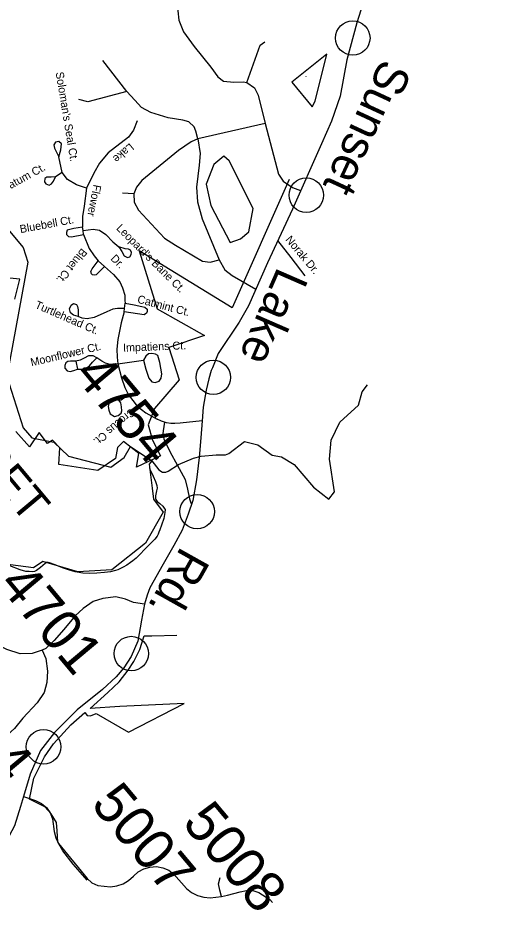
# Model space of a CAD drawing. Extents: x 2054826 to 2060231, y 685508 to 690809.
# Drawn here: x 2058824.2 to 2058951.1, y 689444.4 to 689682.8 of the extents above; entities that cross this region are included whole.
import ezdxf

# ---------------------------------------------------------------- set-up
doc = ezdxf.new("R2010")
doc.units = 0
for name, color, linetype in [('Default', 7, 'Continuous'), ('Old_Level_10', 7, 'Continuous'), ('Old_Level_11', 7, 'Continuous'), ('Old_Level_21', 7, 'Continuous'), ('Old_Level_31', 7, 'Continuous'), ('Old_Level_32', 7, 'Continuous'), ('Old_Level_35', 7, 'Continuous'), ('Old_Level_48', 7, 'Continuous'), ('Old_Level_49', 7, 'Continuous'), ('Old_Level_50', 7, 'Continuous'), ('Old_Level_56', 7, 'Continuous'), ('Old_Level_59', 7, 'Continuous'), ('Old_Level_60', 7, 'Continuous'), ('Old_Level_62', 7, 'Continuous'), ('Old_Level_8', 7, 'Continuous'), ('Sheet Title CELL', 7, 'Continuous')]:
    doc.layers.add(name, color=color, linetype=linetype)

msp = doc.modelspace()

# ---------------------------------------------------------------- linework, layer by layer
at = {"layer": 'Default'}
for centre in [(2058913.43, 689677.45), (2058901.04, 689635.59), (2058876.29, 689587.06), (2058871.97, 689551.29), (2058854.42, 689513.49), (2058831.05, 689488.65)]:
    msp.add_circle(centre, 4.59, dxfattribs=at)
at = {"layer": 'Old_Level_31'}
msp.add_line((2058872.52, 689565.68), (2058872.52, 689565.68), dxfattribs=at)
at = {"layer": 'Old_Level_32'}
for points in [[(2058916.65, 689688.35), (2058914.48, 689681.47), (2058911.85, 689671.65), (2058910.05, 689661.96), (2058907.79, 689655.31), (2058905.13, 689649.29), (2058897.33, 689631.9), (2058890.75, 689617.53), (2058885.69, 689606.14), (2058883.17, 689601.8), (2058877.58, 689593.44)], [(2058877.58, 689593.44), (2058876.06, 689589.61), (2058875.73, 689588.92), (2058875.13, 689586.68), (2058874.41, 689583.61), (2058873.61, 689579.15), (2058873.28, 689575.49)], [(2058873.28, 689575.49), (2058867.45, 689574.9), (2058866.01, 689574.73), (2058865, 689574.77), (2058863.81, 689574.96), (2058862.45, 689575.39), (2058861.33, 689575.93)], [(2058873.28, 689575.49), (2058872.95, 689570.96), (2058872.52, 689565.68)], [(2058872.52, 689565.68), (2058871.84, 689559.76), (2058870.78, 689554.28), (2058869.62, 689550.65), (2058868, 689546.38), (2058865.73, 689542.26), (2058862.9, 689537.28), (2058859.39, 689531), (2058858.63, 689529.02), (2058857.94, 689526.64)], [(2058857.94, 689526.64), (2058857.16, 689522.38), (2058856.15, 689516.79), (2058854.37, 689512.69), (2058852.46, 689509.69), (2058850.36, 689507.28), (2058846.78, 689503.88), (2058840.04, 689498.54), (2058833.98, 689492.46), (2058830.22, 689487.64), (2058827.48, 689481.4), (2058825.7, 689475.43)], [(2058857.94, 689526.64), (2058855.01, 689527.07), (2058852.87, 689527.95), (2058850.34, 689528.58), (2058846.85, 689528.19), (2058844.3, 689527.4), (2058841.65, 689525.45), (2058839.5, 689523.54), (2058836.43, 689519.9), (2058833.9, 689516.96), (2058831.67, 689514.83), (2058830.71, 689514.37)], [(2058830.71, 689514.37), (2058828.04, 689513.53), (2058824.86, 689513.45), (2058821.26, 689514.59), (2058816.88, 689516.82)], [(2058830.71, 689514.37), (2058831.7, 689512.19), (2058832.14, 689508.79), (2058831.94, 689505.78), (2058831.22, 689503.12), (2058829.39, 689500.39), (2058825.51, 689496.27), (2058823.28, 689493.57), (2058820.63, 689491.15), (2058816.62, 689488.34), (2058812.42, 689486.56), (2058808.65, 689485.6), (2058803.34, 689484.86)], [(2058825.7, 689475.43), (2058824.91, 689472.75), (2058823.36, 689467.6), (2058821.22, 689463.57), (2058818.07, 689459.37), (2058815.24, 689456.59), (2058810.85, 689453.12), (2058805.32, 689449.45), (2058799.91, 689445.85), (2058796.17, 689443.35)], [(2058825.7, 689475.43), (2058828.94, 689474.31), (2058830.47, 689473.54), (2058831.84, 689472.5), (2058832.83, 689471.1), (2058833.41, 689469.48), (2058833.91, 689466.09), (2058834.33, 689464.43), (2058835.07, 689462.87), (2058842.65, 689453.58), (2058843.95, 689452.45), (2058845.52, 689451.75), (2058848.93, 689451.39), (2058850.62, 689451.64), (2058852.26, 689452.14), (2058853.73, 689453.04), (2058855.01, 689454.18), (2058856.24, 689455.37), (2058857.75, 689456.19), (2058859.41, 689456.63), (2058861.12, 689456.73), (2058862.81, 689456.41), (2058864.4, 689455.77), (2058865.78, 689454.76), (2058869.17, 689450.88), (2058870.51, 689449.81), (2058872.06, 689449.08), (2058873.72, 689448.63), (2058875.42, 689448.43), (2058878.42, 689448.79)], [(2058878.42, 689448.79), (2058878.01, 689450.46), (2058877.66, 689452.14), (2058878.08, 689453.8)], [(2058878.42, 689448.79), (2058880.1, 689449.11), (2058883.41, 689450.04), (2058885.09, 689450.35), (2058886.81, 689450.37), (2058888.45, 689449.87), (2058891.33, 689448.01), (2058892.01, 689447.14)]]:
    msp.add_lwpolyline(points, dxfattribs=at)
at = {"layer": 'Old_Level_35'}
for p, q in [((2058853.23, 689663.2), (2058846.81, 689671.49)), ((2058890.13, 689654.66), (2058872.17, 689650.57)), ((2058855.13, 689635.91), (2058852.08, 689636.09)), ((2058841.58, 689626.16), (2058841.43, 689627.04)), ((2058841.72, 689625.1), (2058841.58, 689626.16)), ((2058845.62, 689618.12), (2058847.31, 689616.6)), ((2058852.52, 689604.55), (2058852.59, 689605.37)), ((2058852.59, 689605.37), (2058852.77, 689606.86)), ((2058839.66, 689591.41), (2058840.12, 689589.25)), ((2058850.85, 689590.64), (2058857.71, 689591.68))]:
    msp.add_line(p, q, dxfattribs=at)
for points in [[(2058863.87, 689748.2), (2058867.67, 689733.44), (2058869.54, 689726.29), (2058871.57, 689719.78), (2058875.12, 689710.62), (2058875.88, 689706.65), (2058875.79, 689704.51), (2058875.22, 689702.33), (2058873.39, 689699.61), (2058870.38, 689695.04), (2058868.52, 689691.94), (2058867.37, 689688.42), (2058866.85, 689684.74), (2058867.09, 689682.2), (2058868.3, 689679.12), (2058871.21, 689675.23), (2058875.65, 689669.72), (2058877.47, 689667.14), (2058878.95, 689665.98), (2058881.72, 689665.73), (2058884.24, 689665.79), (2058885.25, 689665.61)], [(2058885.25, 689665.61), (2058888.74, 689675.54), (2058890.03, 689676.44)], [(2058885.25, 689665.61), (2058887.26, 689664.22), (2058888.2, 689662.27), (2058890.13, 689654.66)], [(2058853.23, 689663.2), (2058842.81, 689660.46), (2058840.44, 689661.04)], [(2058872.17, 689650.57), (2058871.65, 689652.63), (2058871.19, 689653.79), (2058869.73, 689655.13), (2058868.19, 689655.54), (2058864.24, 689656.17), (2058859.62, 689657.61), (2058857.14, 689658.94), (2058855.35, 689660.87), (2058853.23, 689663.2)], [(2058856, 689655.43), (2058855.03, 689652.91), (2058853.66, 689651.08), (2058848.26, 689646.91), (2058845.96, 689644.13), (2058844.42, 689641.48), (2058842.48, 689637.46)], [(2058890.13, 689654.66), (2058893.68, 689641.22), (2058894.9, 689639.34), (2058897.36, 689637.63), (2058899.54, 689636.81)], [(2058872.17, 689650.57), (2058870.34, 689649.82), (2058866.97, 689647.52), (2058857.22, 689639.54), (2058855.85, 689637.71), (2058855.13, 689635.91)], [(2058872.17, 689650.57), (2058872.76, 689646.72), (2058872.48, 689643.58), (2058871.77, 689637.69), (2058872.07, 689633.85), (2058873.34, 689629.27), (2058877.85, 689618.35)], [(2058836.06, 689641.66), (2058835.13, 689645.84), (2058835.67, 689647.65), (2058835.82, 689649.31), (2058835.13, 689649.93), (2058834.27, 689649.67), (2058833.8, 689649.03), (2058833.99, 689648.1), (2058835.13, 689645.84)], [(2058836.06, 689641.66), (2058834.26, 689640.44), (2058833.12, 689640.4), (2058831.93, 689640.41), (2058831.39, 689640.05), (2058831.27, 689639.19), (2058831.63, 689638.57), (2058832.56, 689638.26), (2058833.14, 689638.57), (2058833.7, 689639.3), (2058834.26, 689640.44)], [(2058842.48, 689637.46), (2058839.86, 689638.34), (2058837.48, 689639.77), (2058836.06, 689641.66)], [(2058842.48, 689637.46), (2058841.89, 689632.63), (2058841.41, 689629.88), (2058841.41, 689627.78), (2058841.43, 689627.04)], [(2058855.13, 689635.91), (2058855.22, 689633.76), (2058856.33, 689631.61), (2058863.29, 689624.11), (2058866.2, 689622.27), (2058873.36, 689618), (2058875.47, 689617.72), (2058877.85, 689618.35)], [(2058841.43, 689627.04), (2058839.12, 689626.7), (2058837.39, 689626.26), (2058837.15, 689625.64), (2058837.19, 689625.09), (2058837.69, 689624.59), (2058838.51, 689624.51), (2058841.72, 689625.1)], [(2058841.58, 689626.16), (2058844.27, 689626.56), (2058845.94, 689626.28), (2058847.61, 689625.08), (2058849.55, 689623.17), (2058851.12, 689621.79), (2058851.93, 689620.62), (2058852.51, 689619.43), (2058853.38, 689618.99), (2058854.04, 689619.2), (2058854.41, 689619.76), (2058854.51, 689620.35), (2058854.24, 689620.97), (2058853.67, 689621.25), (2058852.77, 689621.33), (2058851.12, 689621.79)], [(2058841.72, 689625.1), (2058843.22, 689621.4), (2058844.51, 689619.45), (2058845.62, 689618.12)], [(2058900.74, 689614.08), (2058896.99, 689618.98), (2058893.49, 689623.51)], [(2058847.31, 689616.6), (2058846, 689615.25), (2058845.06, 689614.38), (2058844.55, 689614.28), (2058844.14, 689614.37), (2058843.84, 689614.62), (2058843.67, 689615.23), (2058843.97, 689615.98), (2058845.62, 689618.12)], [(2058877.85, 689618.35), (2058879.39, 689615.7), (2058881.3, 689614.23), (2058887.65, 689610.55)], [(2058847.31, 689616.6), (2058849.7, 689614.45), (2058851.35, 689612.47), (2058852.13, 689610.94), (2058852.69, 689608.97), (2058852.7, 689607.55), (2058852.77, 689606.86)], [(2058852.59, 689605.37), (2058850.77, 689605.44), (2058849.52, 689605.23), (2058847.9, 689604.55), (2058844.51, 689602.97), (2058842.66, 689602.68), (2058841.33, 689602.83), (2058840.27, 689603.29), (2058839.07, 689603.62), (2058838.21, 689604.25), (2058837.98, 689605.32), (2058838.43, 689606.28), (2058839.07, 689606.73), (2058839.82, 689606.44), (2058840.09, 689605.91), (2058840.24, 689605.03), (2058840.27, 689603.29)], [(2058852.77, 689606.86), (2058855.16, 689606.42), (2058857.22, 689605.96), (2058858.07, 689605.75), (2058858.66, 689605.24), (2058858.66, 689604.65), (2058858.47, 689604.16), (2058857.84, 689603.71), (2058852.52, 689604.55)], [(2058852.52, 689604.55), (2058851.74, 689601.63), (2058850.84, 689597.18), (2058850.56, 689594.6), (2058850.64, 689592.4), (2058850.85, 689590.64)], [(2058857.71, 689591.68), (2058858.31, 689589.25), (2058859.06, 689586.85), (2058859.88, 689585.86), (2058860.83, 689585.73), (2058861.86, 689586.01), (2058862.35, 689586.83), (2058862.54, 689588), (2058862.04, 689591.02), (2058861.52, 689592.85), (2058860.91, 689593.27), (2058859.92, 689593.45), (2058859.04, 689593.3), (2058858.3, 689592.68), (2058857.71, 689591.68)], [(2058850.85, 689590.64), (2058848.81, 689590.45), (2058847.58, 689590.82), (2058846.55, 689591.38), (2058845.24, 689592.26), (2058844.29, 689592.81), (2058843.06, 689592.84), (2058841.89, 689592.21), (2058840.8, 689591.66), (2058839.66, 689591.41), (2058838.24, 689591.42), (2058837.49, 689591.3), (2058836.96, 689590.92), (2058836.7, 689590.21), (2058836.72, 689589.52), (2058837.31, 689588.81), (2058838.18, 689588.62), (2058839.16, 689588.88), (2058840.12, 689589.25), (2058841.12, 689589.24), (2058842.38, 689589.52), (2058843.28, 689590.13), (2058844.1, 689591.09), (2058845.24, 689592.26)], [(2058850.85, 689590.64), (2058851.85, 689586.98), (2058852.69, 689584.37), (2058853.68, 689582.43)], [(2058853.68, 689582.43), (2058851.7, 689580.99), (2058851.23, 689580.88), (2058850.21, 689581.08), (2058849.31, 689580.97), (2058848.74, 689580.64), (2058848.46, 689580.05), (2058848.27, 689579.26), (2058848.42, 689578.32), (2058848.83, 689577.32), (2058849.93, 689576.68), (2058850.91, 689576.87), (2058851.73, 689577.49), (2058851.9, 689578.12), (2058851.85, 689579.21), (2058851.67, 689580.26), (2058851.23, 689580.88)], [(2058853.68, 689582.43), (2058856.03, 689579.36), (2058858.34, 689577.61), (2058861.33, 689575.93)], [(2058863.31, 689575.12), (2058862.92, 689572.81), (2058862.86, 689572.06), (2058862.93, 689571.38), (2058863.06, 689570.7), (2058863.78, 689569.13), (2058865.27, 689566.35), (2058867.21, 689562.8), (2058868.74, 689559.86), (2058869.38, 689557.32), (2058869.91, 689554.69), (2058870.19, 689553.87), (2058870.46, 689553.29)]]:
    msp.add_lwpolyline(points, dxfattribs=at)
at = {"layer": 'Old_Level_48'}
for points in [[(2058906.53, 689673.18), (2058897.16, 689665.67), (2058902.62, 689659.14), (2058903.37, 689660.59), (2058906.53, 689673.18)], [(2058896.5, 689639.74), (2058881.26, 689605.54), (2058856.55, 689620.77), (2058861.31, 689605.31)], [(2058823.43, 689607.92), (2058824.78, 689613.19), (2058810.24, 689614.6)], [(2058861.31, 689605.31), (2058873.89, 689598.18), (2058864.47, 689595.04)], [(2058864.47, 689595.04), (2058867.14, 689586.37), (2058860.57, 689578.8), (2058858.92, 689574.44), (2058860.06, 689570.32), (2058862.19, 689566.12), (2058855.79, 689563.18), (2058856.48, 689566.75), (2058852.38, 689570), (2058850.74, 689568.39), (2058850.22, 689565.43), (2058845.55, 689562.21), (2058835.17, 689563.88), (2058835.43, 689568.25), (2058833.48, 689570.3), (2058832.15, 689569.42), (2058829.91, 689572.37), (2058827.31, 689568.59), (2058823.67, 689572.68)], [(2058842.69, 689453.13), (2058838.95, 689457.4), (2058836.17, 689460.91), (2058834.84, 689463.26), (2058834.68, 689466.27), (2058834.54, 689468.52), (2058833.11, 689470.79), (2058831.39, 689472.65), (2058827.29, 689474.74), (2058828.47, 689480.29), (2058829.82, 689483), (2058831.28, 689485.95), (2058833.74, 689489.42), (2058838.3, 689494.5), (2058842.02, 689497.77), (2058842.64, 689497.03), (2058843.57, 689496.86), (2058845.09, 689497.5), (2058853.65, 689492.53), (2058868.48, 689500.21), (2058851.34, 689499.43), (2058843.49, 689498.84), (2058848.21, 689503.1), (2058851.2, 689505.92), (2058853.62, 689509.05), (2058855.12, 689511.4), (2058856.69, 689514.61), (2058857.82, 689518.23), (2058859.87, 689518.21), (2058866.6, 689518.36)]]:
    msp.add_lwpolyline(points, dxfattribs=at)
at = {"layer": 'Old_Level_49'}
for points in [[(2058906.53, 689673.18), (2058897.16, 689665.67), (2058902.62, 689659.14), (2058903.37, 689660.59), (2058906.53, 689673.18)], [(2058896.5, 689639.74), (2058881.26, 689605.54), (2058856.55, 689620.77), (2058861.31, 689605.31)], [(2058823.43, 689607.92), (2058824.78, 689613.19), (2058810.24, 689614.6)], [(2058861.31, 689605.31), (2058873.89, 689598.18), (2058864.47, 689595.04)], [(2058864.47, 689595.04), (2058867.14, 689586.37), (2058860.57, 689578.8), (2058858.92, 689574.44), (2058860.06, 689570.32), (2058862.19, 689566.12), (2058855.79, 689563.18), (2058856.48, 689566.75), (2058852.38, 689570), (2058850.74, 689568.39), (2058850.22, 689565.43), (2058845.55, 689562.21), (2058835.17, 689563.88), (2058835.43, 689568.25), (2058833.48, 689570.3), (2058832.15, 689569.42), (2058829.91, 689572.37), (2058827.31, 689568.59), (2058823.67, 689572.68)], [(2058842.69, 689453.13), (2058838.95, 689457.4), (2058836.17, 689460.91), (2058834.84, 689463.26), (2058834.68, 689466.27), (2058834.54, 689468.52), (2058833.11, 689470.79), (2058831.39, 689472.65), (2058827.29, 689474.74), (2058828.47, 689480.29), (2058829.82, 689483), (2058831.28, 689485.95), (2058833.74, 689489.42), (2058838.3, 689494.5), (2058842.02, 689497.77), (2058842.64, 689497.03), (2058843.57, 689496.86), (2058845.09, 689497.5), (2058853.65, 689492.53), (2058868.48, 689500.21), (2058851.34, 689499.43), (2058843.49, 689498.84), (2058848.21, 689503.1), (2058851.2, 689505.92), (2058853.62, 689509.05), (2058855.12, 689511.4), (2058856.69, 689514.61), (2058857.82, 689518.23), (2058859.87, 689518.21), (2058866.6, 689518.36)]]:
    msp.add_lwpolyline(points, dxfattribs=at)
at = {"layer": 'Old_Level_50'}
msp.add_line((2058873.06, 689566.08), (2058873.06, 689566.08), dxfattribs=at)
at = {"layer": 'Old_Level_56'}
msp.add_line((2058900.9, 689667.26), (2058900.91, 689667.21), dxfattribs=at)
at = {"layer": 'Old_Level_59'}
msp.add_line((2058864.29, 689562.07), (2058867.05, 689563.85), dxfattribs=at)
for points in [[(2058880.74, 689623), (2058883.54, 689623.94), (2058885.75, 689625.79), (2058886.87, 689632.06), (2058880.51, 689644.75), (2058879.08, 689646.02), (2058876.38, 689643.76), (2058874.41, 689638.55), (2058875.58, 689632.84), (2058880.74, 689623)], [(2058907.06, 689554.6), (2058908.59, 689556.6), (2058907.21, 689565.31), (2058907.69, 689570.34), (2058910.01, 689575.11), (2058914.98, 689579.65), (2058915.93, 689583.24), (2058917.32, 689585.04)], [(2058867.05, 689563.85), (2058871.02, 689565.53), (2058873.06, 689566.08), (2058877.03, 689566.39), (2058879.5, 689566.44), (2058880.43, 689566.81), (2058884.57, 689570.02), (2058888.16, 689569.13), (2058891.93, 689566.3), (2058894.42, 689565.93), (2058897.86, 689563.85), (2058902.94, 689557.85), (2058907.06, 689554.6)], [(2058859.88, 689564.84), (2058861.77, 689562.44), (2058862.7, 689561.85), (2058863.59, 689561.79), (2058864.29, 689562.07)]]:
    msp.add_lwpolyline(points, dxfattribs=at)
at = {"layer": 'Old_Level_60'}
msp.add_lwpolyline([(2058822, 689626.02), (2058825.64, 689621.66), (2058826.88, 689617.73), (2058821.27, 689587.25), (2058825.67, 689573.59), (2058827.95, 689570.92), (2058833.78, 689569.78), (2058837.73, 689566.05), (2058848.96, 689563.12), (2058852.5, 689565.7), (2058854.26, 689568.61), (2058859.88, 689564.84), (2058859.23, 689563.96), (2058859.97, 689557.53), (2058860.31, 689554.6), (2058862.95, 689551.14), (2058858.2, 689542.92), (2058849.29, 689535.81), (2058840.18, 689535.23), (2058830.84, 689538.01), (2058828.39, 689536.3), (2058816.76, 689537.84)], dxfattribs=at)
at = {"layer": 'Old_Level_62'}
msp.add_lwpolyline([(2058859.27, 689562.88), (2058859.4, 689562.65), (2058860.24, 689560.72), (2058860.91, 689559.33), (2058861.09, 689558.81), (2058861.22, 689558.23), (2058861.3, 689557.54), (2058861.19, 689556.86), (2058860.89, 689555.49), (2058860.88, 689554.81), (2058861, 689554.56), (2058861.16, 689554.28), (2058861.32, 689553.98), (2058862, 689553.46), (2058862.87, 689552.74), (2058863.19, 689552.25), (2058863.43, 689551.87), (2058863.4, 689551.08), (2058863.06, 689549.5), (2058862.47, 689547.65), (2058862.04, 689546.45), (2058861.8, 689545.82), (2058861.57, 689545.29), (2058861.29, 689544.72), (2058860.67, 689543.94), (2058859.49, 689542.71), (2058858.04, 689541.32), (2058856.71, 689539.86), (2058855.7, 689538.93), (2058854.86, 689538.22), (2058854.26, 689537.71), (2058853.23, 689537.02), (2058852.27, 689536.46), (2058851.55, 689536.11), (2058850.86, 689535.8), (2058850.21, 689535.58), (2058848.93, 689535.27), (2058847.3, 689535.1), (2058845.21, 689534.87), (2058843.22, 689534.81), (2058841.52, 689534.92), (2058839.52, 689535.27), (2058837.72, 689535.8), (2058836.11, 689536.3), (2058834.14, 689537.12), (2058832.63, 689537.62), (2058832.26, 689537.75), (2058831.95, 689537.72), (2058831.51, 689537.44), (2058830.26, 689536.4), (2058829.22, 689535.61), (2058828.66, 689535.38), (2058828.04, 689535.3), (2058827.26, 689535.32), (2058826.35, 689535.39), (2058824.85, 689535.77), (2058822.09, 689536.83)], dxfattribs=at)

# ---------------------------------------------------------------- texts
at = {"layer": 'Old_Level_10'}
for s, height, rotation, p in [("Soloman's Seal Ct.", 2.1325, 279.4119, (2058834.27, 689668.25)), ('Lake', 2.133, 219.9844, (2058854.03, 689649.58)), ('Ageratum Ct.', 2.1325, 28.6134, (2058817.03, 689634.33)), ('Flower', 2.133, 258.5338, (2058844.39, 689638.54)), ('Bluebell Ct.', 2.1325, 10.5825, (2058824.94, 689625.47)), ("Leopard's Bane Ct.", 2.1325, 315.1102, (2058850.28, 689626.61)), ('Norak Dr.', 2.133, 309.9093, (2058895.36, 689623.69)), ('Bluet Ct.', 2.133, 230.5159, (2058841.23, 689621.6)), ('Dr.', 2.133, 315.1103, (2058848.74, 689618.54)), ('Turtlehead Ct.', 2.1325, 336.5034, (2058828.59, 689605.62)), ('Catmint Ct.', 2.1325, 345.161, (2058855.88, 689606.98)), ('Moonflower Ct.', 2.1325, 13.3732, (2058827.86, 689589.99)), ('Impatiens Ct.', 2.1325, 2.2098, (2058852.28, 689593.9)), ('Crocus Ct.', 2.133, 219.9093, (2058854.44, 689579.04))]:
    msp.add_text(s, height=height, rotation=rotation, dxfattribs=at).set_placement(p)
at = {"layer": 'Old_Level_11'}
for s, rotation, p in [('Sunset', 245.1013, (2058921.18, 689672.28)), ('Lake', 246.4652, (2058893.5, 689616.77)), ('Rd.', 240.7562, (2058867.77, 689542.32))]:
    msp.add_text(s, height=8.997, rotation=rotation, dxfattribs=at).set_placement(p)
at = {"layer": 'Old_Level_21'}
msp.add_text('SUNSET', height=8.797, rotation=309.9093, dxfattribs=at).set_placement((2058795.92, 689584.45))
at = {"layer": 'Old_Level_8'}
for s, p in [('4754', (2058838.82, 689587.68)), ('4701', (2058818.76, 689531.73)), ('4704', (2058800.09, 689503.1)), ('5007', (2058843.4, 689473.25)), ('5008', (2058867.73, 689468.27))]:
    msp.add_text(s, height=10.796, rotation=309.9093, dxfattribs=at).set_placement(p)
at = {"layer": 'Sheet Title CELL'}
msp.add_text('See Sheet 1-B For Conventional Symbols', height=11.25, rotation=309.6672, dxfattribs=at).set_placement((2058849.68, 689895.6))

doc.saveas('drawing.dxf')
